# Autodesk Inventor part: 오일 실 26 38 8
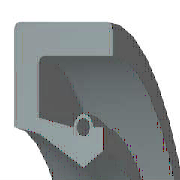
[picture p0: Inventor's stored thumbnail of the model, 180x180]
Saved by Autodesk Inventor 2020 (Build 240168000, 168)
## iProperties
IsCustomPart: 1
Created: 2012-02
Part Number: 오일 실 26 38 8
Material: 고무
Description: 오일-실
Document SubType Name: Modeling
Standard: KS B 2804
Designer: mduedu
Standards Organization: KS
Language: ko-KR
Size Designation: S - 26 38 8
Categories: <MemberInstance><Categories><Category DisplayName="샤프트 부품" InternalName="7f7aeb1f-a693-4053-b835-cee3144e0d98" Mnemonic="SHFT"><Category DisplayName="실링" Intern
Density: 0.93 g/cm^3
Appearance: 고무 - 검은색 - 버전 1.1
Author: mduedu
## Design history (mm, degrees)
revolve "본체" stored, may be unused: angle "d17" = 90 deg
revolve "스프링1" stored, may be unused: angle "d18" = 90 deg
body "Solid1"
sketch "스케치1"
  geometry: L1 (0, 19)-(8, 19); L2 (8, 19)-(8, 17.75); L3 (8, 17.75)-(1.75, 17.75); L4 (0, 19)-(0, 15.1); L5 (0, 15.1)-(1.75, 14.75); L6 (1.75, 14.75)-(4.9, 13); L7 (4.9, 13)-(0, 13); L8 (6.3, 13.875)-(6.3, 15.1); L9 (0, 0)-(9.586, 0) reference; L10 (4.9, 13)-(6.3, 13.875); L11 (0, 18)-(0, -3) reference; L12 (-1.917, 0)-(11.503, 0) reference; L13 (4.2, 15.1)-(1.75, 15.59); L14 (1.75, 15.59)-(1.75, 17.75); L15 (6.3, 15.1)-(5.6, 15.1); C1 r 0.455 at (4.9, 15.1); A1 r 0.7 centre (4.9, 15.1) between (5.6, 15.1) and (4.2, 15.1)
  constraints: 26 end point, 5 horizontal alignment, 4 perpendicular, 2 centre point, 2 collinear, 2 horizontal, 2 parallel, 2 point on circle, 2 point on line, 2 vertical alignment, 1 coincident
  dimensions: "d0" = 38 diameter of L1 L9 (= SD2); "d1" = 27.75 diameter of L8.start L9 (= ABDM); "d2" = 1.25 distance of L1.end L2.end (computed from SD); "d3" = 0.91 diameter of C1 (= SPDI); "d4" = 1.4 diameter of A1 (= SPDA); "d5" = 26 diameter of L6.end L9 (= NND); "d6" = 29.5 diameter of L5.end L9 (= TKDM); "d7" = 30.2 diameter of L4.end L9 (= HLDM); "d8" = 4.9 distance from line of C1.centre L4 (= SPDST); "d9" = 6.3 distance between parallel lines of L8 L4 (= SDI); "d10" = 8 distance between parallel lines of L2 L4 (= SWDT); "d12" = 1.75 distance between parallel lines of L14 L4 (= SD)
fillet "모깎기1" dims "d11" = 0.3 (= RR)
other parameters: "SD2" = 38 [user parameter; used in 1 equation term], "SWDT" = 8 [user parameter; used in 1 equation term], "RR" = 0.3 [user parameter; used in 1 equation term], "SD" = 1.75 [user parameter; used in 2 equation terms], "NND" = 26 [user parameter; used in 1 equation term], "SPDA" = 1.4 [user parameter; used in 1 equation term], "SPDI" = 0.91 [user parameter; used in 1 equation term], "TKDM" = 29.5 [user parameter; used in 1 equation term], "HLDM" = 30.2 [user parameter; used in 1 equation term], "ABDM" = 27.75 [user parameter; used in 1 equation term], "SDI" = 6.3 [user parameter; used in 1 equation term], "SPDST" = 4.9 [user parameter; used in 1 equation term], "d13" = 0, "d14" = 0, "d15" = 0, "LAB" = 0.35 [user parameter]
